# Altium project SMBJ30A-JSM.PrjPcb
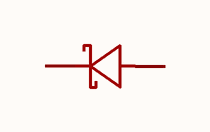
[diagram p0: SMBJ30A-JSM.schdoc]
1 sheet, 1 parts. Net scope: global (net labels, ports and power ports of the same name join across sheets).

## Sheet SMBJ30A-JSM.schdoc
size 127 x 101 mm

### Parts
D?  smbj30a-jsm  [SMB_L4.3-W3.6-LS5.3-RD]  (value not drawn)

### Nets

Not connected (* = marked no-connect by the designer): D? 1(K) 2(A)

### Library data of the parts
D? = smbj30a-jsm: 极性:单向;反向截止电压(Vrwm):30V;钳位电压:48.4V;峰值脉冲电流(Ipp):12.4A;峰值脉冲功率(Ppp):600W;击穿电压(VBR):36.8V;; Manufacturer: JSMSEMI(杰盛微); AddInBom: yes; ModelId: 314c1f1e2ff843d9bed33f9992fd5d20; ModelName: SMB_L4.32-W3.62-LS5.3-RD; ModelTransform: 208.661,142.5194,0,0,0,0,0,0,0; Polarity: 单向; Reverse Stand-Off Voltage (Vrwm): 30V; Clamping Voltage: 48.4V; Peak Pulse Current (Ipp): 12.4A; Peak Pulse Power Dissipation (Ppp): 600W; Voltage - Breakdown: 36.8V; Reverse Leakage Current (Ir): 1uA; Number of Channels: 单路; Type: TVS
